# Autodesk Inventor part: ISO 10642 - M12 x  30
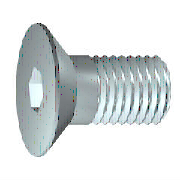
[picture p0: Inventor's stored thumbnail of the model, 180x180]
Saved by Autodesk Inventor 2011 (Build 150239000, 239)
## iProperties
IsCustomPart: 0
Created: 2010-02
Part Number: ISO 10642 - M12 x  30
Material: Steel
Description: Hexagon Socket Countersunk Head Screw-1 - Product grade A
Document SubType Name: Modeling
Standard: ISO 10642
Designer: 129877
Standard Revision: Second edition 2004-03-01
Standards Organization: ISO
Language: en-US
Size Designation: M12 x  30
Categories: <MemberInstance><Categories><Category DisplayName="Fasteners" InternalName="e4da775c-781d-43d5-af7c-5136215cf5a6" Mnemonic="FSTN"><Category DisplayName="Bolts"
Density: 7.85 g/cm^3
Mass: 34.2749 g
Surface Area: 20.8744 cm^2
Volume: 4.36623 cm^3
Author: 129877
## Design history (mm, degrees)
body "Solid1"
workplane "Work Plane1"
revolve "Body" stored, may be unused: angle "d13" = 90 deg
sketch "Sketch2"
  geometry: L1 (0, -16.184)-(0, 16.184) reference; L2 (-16.184, 0)-(16.184, 0) reference; L3 (4.619, 0)-(2.309, -4); L4 (2.309, -4)-(-2.309, -4); L5 (-2.309, -4)-(-4.619, 0); L6 (-4.619, 0)-(-2.309, 4); L7 (-2.309, 4)-(2.309, 4); L8 (2.309, 4)-(4.619, 0); A1 r 4.619 centre (0, 0) between (0, 4.619) and (4.619, 0) reference; 2 further points
  constraints: 12 end point, 2 coincident, 2 point on circle, 2 point on line, 12 other
extrude "Slot" join sketch "Sketch2" taper "d14" = 0 deg; stored distance "d30" = 10
feature "Thread" dims "d15" = 16.5 (= GEL), "d16" = 0
chamfer "Chamfer1" distance "d17" = 1.07354 (= -0.5 x SPD + 0.5 x GD); stored, may be unused: second distance "d18" = 1.07354 (= GUL), angle "d39" = 45 deg
sketch "Sketch1"
  geometry: L1 (30, 0)-(30, 6); L2 (30, 6)-(13.5, 6); L3 (13.5, 6)-(12.426, 6); L4 (0, 11.56)-(0, 4.619); L5 (0, 4.619)-(5.19, 4.619); L6 (5.19, 4.619)-(7.857, 0); L7 (7.857, 0)-(30, 0); L8 (0, 11.56)-(1.88, 11.56); L9 (1.88, 11.56)-(7.44, 6); L10 (12.426, 6)-(7.44, 6); L11 (13.5, 6)-(7.44, 6); L12 (7.44, 6)-(7.44, 6); L13 (-6, 0)-(36, 0) reference; L14 (0, -2.312)-(0, 13.872) reference
  constraints: 24 end point, 4 collinear, 3 parallel
  dimensions: "d0" = 30 distance between parallel lines of L4 L1 (= NLG); "d1" = 16.5 distance from line of L2.end L1 (= GEL); "d2" = 5.19 distance from line of L5.end L4 (= INTI); "d3" = 12 diameter of L2 L7 (= GD); "d6" = 7.44 distance from line of L9.end L4 (= KOH); "d7" = 45 deg angle of L9 L7 (= 0.5 x SEWI); "d8" = 9.2376 diameter of L5 L7 (= 1.1547 x SW); "d9" = 60 deg angle of L6 L7; "d10" = 23.12 diameter of L8 L7 (= KOD); "d11" = 12 diameter of L10 L7 (= BDM); "d12" = 1.07354 distance of L3.end L2.end (= GAL)
other parameters: "NLG" = 30 [user parameter; used in 1 equation term], "INTI" = 5.19 [user parameter; used in 1 equation term], "GEL" = 16.5 [user parameter; used in 2 equation terms], "GAL" = 1.07354 (= 0.61345 x PTC) [user parameter; used in 1 equation term], "KOH" = 7.44 [user parameter; used in 1 equation term], "KOD" = 23.12 [user parameter; used in 1 equation term], "GUL" = 1.07354 (= 0.61345 x PTC) [user parameter; used in 1 equation term], "SPD" = 9.85293 (= NND - 1.2269 x PTC) [user parameter; used in 1 equation term], "BDM" = 12 (= NND) [user parameter; used in 1 equation term], "GD" = 12 (= NND) [user parameter; used in 2 equation terms], "SEWI" = 90 deg [user parameter; used in 1 equation term], "d20" = 0, "SW" = 8 [user parameter; used in 1 equation term], "d43" = 0, "d44" = 0, "TOA" = 30 deg [user parameter], "GD1" = 9.85293 (= THREADDIA - 1.2269 x PTC) [user parameter], "EPV" = 13.44 [user parameter], "THREADDIA" = 12 [user parameter; used in 1 equation term], "TPU" = 5.71429 (computed from PTC) [user parameter], "PTC" = 1.75 [user parameter; used in 5 equation terms], "NND" = 12 [user parameter; used in 3 equation terms], "E0" = 9.24 [user parameter], "THREADDESC" = 12.345 [user parameter]
